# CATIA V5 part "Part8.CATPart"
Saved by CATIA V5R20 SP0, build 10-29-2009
Part number: 3JT7.5X2X11.5
Revision: ANY
Definition: UNKNOWN
Nomenclature: 3JT7.5X2X11.5
Source: Unknown
Bounding box of the stored display mesh (mm): x -5.75 to 5.75, y -5.75 to 5.75, z -1 to 1
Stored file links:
  C:\Users\Utente\Desktop\IO LAVORO\3D X SITO CF\CUMSA\3D files PW\pw060830\pw060830_injection\Part8.CATPart
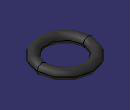
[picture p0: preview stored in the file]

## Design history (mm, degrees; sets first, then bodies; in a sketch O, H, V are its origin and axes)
Body1 "Revolución1" (main body)
  Solid1: solid without history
